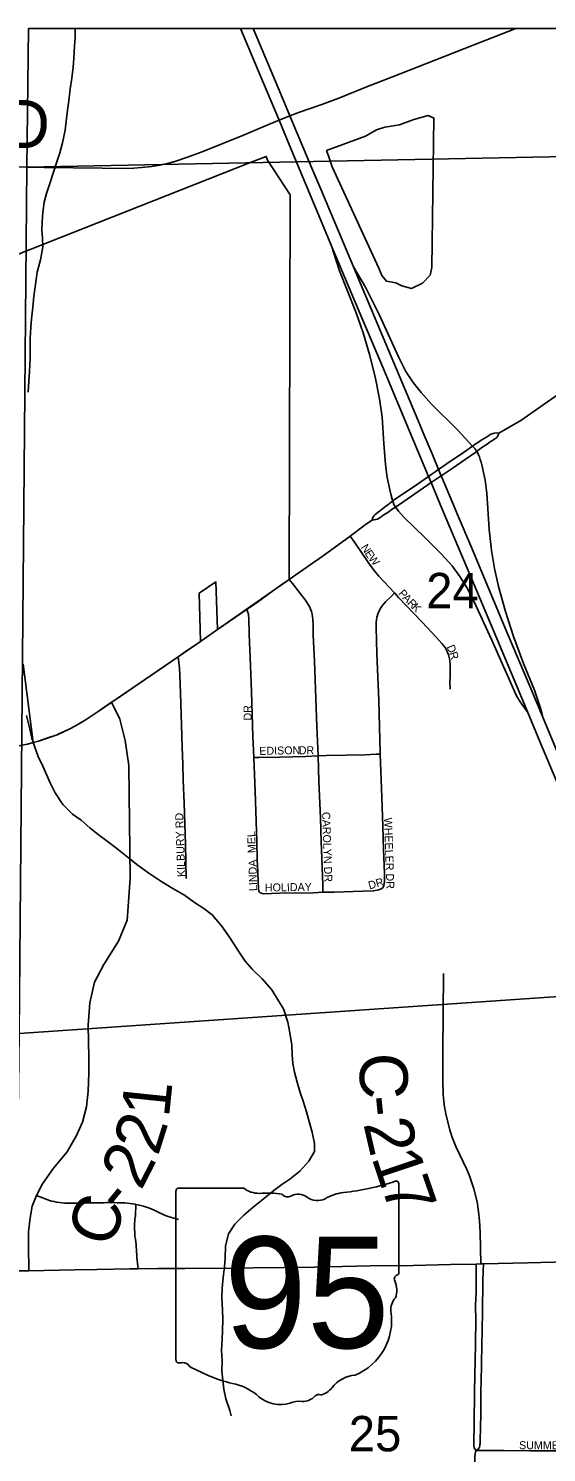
# Model space of a CAD drawing. Extents: x -9.1 to 34, y -3.1 to 22.
# Drawn here: x 7.252 to 7.865, y 19.215 to 20.9 of the extents above; entities that cross this region are included whole.
import ezdxf

# ---------------------------------------------------------------- set-up
doc = ezdxf.new("R2010")
doc.units = 0
for name, color, linetype in [('GM_X_Corporation', 7, 'Continuous'), ('GM_X_County_Road', 7, 'Continuous'), ('GM_X_County_Road_Text', 7, 'Continuous'), ('GM_X_Interchange_Ramps', 7, 'Continuous'), ('GM_X_Minor_Lake', 7, 'Continuous'), ('GM_X_Minor_River', 7, 'Continuous'), ('GM_X_Section', 7, 'Continuous'), ('GM_X_Section_Text', 7, 'Continuous'), ('GM_X_State_Location', 7, 'Continuous'), ('GM_X_State_Route', 7, 'Continuous'), ('GM_X_State_Shield', 7, 'Continuous'), ('GM_X_Township_Road', 7, 'Continuous'), ('GM_X_Township_Subdivision', 7, 'Continuous'), ('GM_X_Township_Subdivision_Text', 7, 'Continuous'), ('GM_X_US_Route', 7, 'Continuous')]:
    doc.layers.add(name, color=color, linetype=linetype)

msp = doc.modelspace()

# ---------------------------------------------------------------- linework, layer by layer
at = {"layer": 'GM_X_Corporation'}
msp.add_lwpolyline([(7.2455, 20.1477), (7.2573, 20.0548), (7.2636, 20.0565), (7.2747, 20.0604), (7.2857, 20.0642), (7.2875, 20.065), (7.2997, 20.0707), (7.308, 20.075), (7.3133, 20.0782), (7.3187, 20.0813), (7.3343, 20.0916), (7.4289, 20.1565), (7.4552, 20.1744), (7.4538, 20.2315), (7.4735, 20.2449), (7.4756, 20.1885), (7.5601, 20.2479), (7.5614, 20.7031), (7.5347, 20.7443), (7.5331, 20.7485), (7.5132, 20.7408), (6.9954, 20.5365)], dxfattribs=at)
at = {"layer": 'GM_X_County_Road'}
for points in [[(7.2303, 20.7363), (7.2707, 20.7355), (7.3391, 20.7345), (7.3639, 20.7343), (7.3763, 20.7346), (7.3856, 20.7353), (7.3979, 20.7368), (7.407, 20.7383), (7.4161, 20.7403), (7.425, 20.7427), (7.4398, 20.7475), (7.4572, 20.754), (7.5062, 20.7738), (7.5349, 20.7858), (7.5483, 20.7914), (7.555, 20.7942), (7.5612, 20.7966), (7.5725, 20.8008), (7.5989, 20.8099), (7.6192, 20.8177), (7.6509, 20.8305), (7.6828, 20.8428), (7.732, 20.8621), (7.7783, 20.8802), (7.8286, 20.9)], [(7.2612, 19.5187), (7.2682, 19.5324), (7.2812, 19.5513), (7.2973, 19.5705), (7.3086, 19.5898), (7.3156, 19.6057), (7.3203, 19.6237), (7.3225, 19.6423), (7.323, 19.6636), (7.3233, 19.6821), (7.3224, 19.7204), (7.3242, 19.7469), (7.3297, 19.7714), (7.3408, 19.7923), (7.3581, 19.8199), (7.3686, 19.8448), (7.3722, 19.894), (7.3705, 20.0279), (7.3661, 20.0572), (7.36, 20.0827), (7.3501, 20.1025)], [(7.7424, 19.6881), (7.743, 19.7814)], [(7.7873, 19.4379), (7.7864, 19.475), (7.7857, 19.4887), (7.7846, 19.4998), (7.7827, 19.5113), (7.7788, 19.5267), (7.7736, 19.5421), (7.7705, 19.5496), (7.7577, 19.5767), (7.753, 19.5885), (7.7504, 19.5967), (7.7462, 19.6134), (7.7439, 19.626), (7.7427, 19.6385), (7.7422, 19.6553), (7.7424, 19.6881)], [(7.2521, 19.4298), (7.2518, 19.4597), (7.2518, 19.4759), (7.2535, 19.4922), (7.2561, 19.5063), (7.2612, 19.5187)], [(7.2612, 19.5187), (7.2766, 19.5128), (7.279, 19.5122), (7.2821, 19.5115), (7.2849, 19.511), (7.2883, 19.5105), (7.2914, 19.5102), (7.2947, 19.5099), (7.2976, 19.5097), (7.3007, 19.5097), (7.3038, 19.5098), (7.3069, 19.5098), (7.31, 19.5098), (7.3131, 19.5099), (7.3162, 19.5099), (7.3193, 19.51), (7.3224, 19.51), (7.3256, 19.5101), (7.3287, 19.5101), (7.3318, 19.5101), (7.3349, 19.5102), (7.338, 19.5103), (7.3411, 19.5103), (7.3442, 19.5104), (7.3473, 19.5104), (7.3504, 19.5105), (7.3535, 19.5106), (7.3566, 19.5103), (7.3599, 19.5103), (7.3629, 19.5102), (7.3658, 19.51), (7.3688, 19.5098), (7.3718, 19.5095), (7.3747, 19.509), (7.3776, 19.5085), (7.3787, 19.5083)], [(7.3816, 19.432), (7.38, 19.4454), (7.3801, 19.449), (7.3795, 19.4519), (7.3795, 19.4549), (7.3793, 19.4578), (7.3791, 19.4607), (7.3788, 19.4636), (7.3784, 19.4671), (7.3777, 19.4701), (7.3777, 19.4732), (7.3774, 19.4759), (7.3772, 19.4786), (7.3771, 19.4828), (7.3772, 19.4856), (7.3774, 19.4884), (7.3776, 19.4912), (7.3784, 19.4949), (7.3787, 19.5083)]]:
    msp.add_lwpolyline(points, dxfattribs=at)
at = {"layer": 'GM_X_Interchange_Ramps'}
for points in [[(7.6109, 20.6417), (7.6158, 20.6252), (7.6198, 20.6133), (7.6397, 20.5634), (7.6479, 20.5399), (7.6559, 20.5131), (7.6625, 20.4859), (7.6673, 20.4615), (7.6702, 20.4399), (7.6724, 20.4089), (7.6743, 20.3841), (7.6764, 20.3687), (7.6803, 20.3505), (7.6807, 20.3489), (7.6821, 20.343), (7.6829, 20.3408), (7.6844, 20.3368)], [(7.7803, 20.4023), (7.7788, 20.404), (7.7772, 20.4057), (7.7595, 20.4248), (7.7289, 20.4553), (7.7165, 20.4691), (7.707, 20.4812), (7.6986, 20.4941), (7.69, 20.5105), (7.667, 20.5614), (7.6605, 20.5743), (7.6506, 20.5939), (7.6364, 20.6178)], [(7.8607, 20.0848), (7.8578, 20.0956), (7.8536, 20.1084), (7.8508, 20.1167), (7.8376, 20.1483), (7.8257, 20.1803), (7.8163, 20.2098), (7.808, 20.2397), (7.8034, 20.2608), (7.7999, 20.2823), (7.7971, 20.3069), (7.7945, 20.3502), (7.7924, 20.3655), (7.7884, 20.3837), (7.7875, 20.3868), (7.7866, 20.3898), (7.7855, 20.3929), (7.7846, 20.3953), (7.7836, 20.3975), (7.7823, 20.3995), (7.7814, 20.4008), (7.7803, 20.4023)], [(7.6844, 20.3368), (7.6859, 20.3341), (7.6862, 20.3336), (7.6881, 20.3309), (7.6899, 20.3286), (7.696, 20.3215), (7.7208, 20.2977), (7.7407, 20.2778), (7.7531, 20.2639), (7.7625, 20.2514), (7.7708, 20.2382), (7.7795, 20.2216), (7.8002, 20.1761), (7.8296, 20.1103), (7.8338, 20.1031), (7.8428, 20.0904)]]:
    msp.add_lwpolyline(points, dxfattribs=at)
at = {"layer": 'GM_X_Minor_Lake'}
for points in [[(7.6045, 20.7554), (7.6071, 20.7482), (7.6112, 20.7364), (7.6616, 20.6267), (7.6665, 20.6164), (7.6699, 20.6077), (7.6755, 20.6009), (7.6865, 20.5989), (7.6937, 20.5955), (7.7051, 20.5924), (7.7183, 20.5984), (7.7271, 20.6082), (7.729, 20.6173), (7.7316, 20.7939), (7.7248, 20.797), (7.7077, 20.7921), (7.691, 20.7861), (7.6736, 20.7832), (7.6637, 20.7802), (7.6508, 20.7726)], [(7.6508, 20.7726), (7.6045, 20.7554)]]:
    msp.add_lwpolyline(points, dxfattribs=at)
at = {"layer": 'GM_X_Minor_River'}
for points in [[(7.2658, 20.6263), (7.2686, 20.6415), (7.2682, 20.6517), (7.2675, 20.6612), (7.2679, 20.671), (7.2687, 20.6824), (7.2703, 20.6945), (7.273, 20.7047), (7.2779, 20.7187), (7.281, 20.7286), (7.2852, 20.7422), (7.2887, 20.7528), (7.2921, 20.7645), (7.2952, 20.7797), (7.2968, 20.7933), (7.298, 20.8032), (7.2995, 20.8145), (7.3011, 20.8286), (7.3031, 20.8411), (7.3046, 20.8543), (7.3054, 20.8646), (7.3062, 20.8793), (7.307, 20.8888), (7.3071, 20.9)], [(7.2512, 20.4695), (7.252, 20.4827), (7.2528, 20.4941), (7.2536, 20.51), (7.2537, 20.5335), (7.2545, 20.546), (7.2553, 20.5562), (7.2569, 20.5702), (7.2581, 20.5831), (7.26, 20.5971), (7.262, 20.6115), (7.2658, 20.6263)], [(7.4811, 19.4092), (7.4823, 19.4217), (7.4838, 19.4342), (7.4846, 19.4445), (7.4851, 19.4589), (7.4885, 19.4733), (7.4958, 19.485), (7.5068, 19.4955), (7.5178, 19.505), (7.5315, 19.5159), (7.5422, 19.5246), (7.5517, 19.5318), (7.5612, 19.5382), (7.573, 19.5476), (7.5836, 19.5593), (7.5901, 19.571), (7.5901, 19.5805), (7.5875, 19.5938), (7.5845, 19.6048), (7.5808, 19.6177), (7.5767, 19.6306), (7.5733, 19.6405), (7.5699, 19.653), (7.5666, 19.6647), (7.5647, 19.675), (7.564, 19.6852), (7.5633, 19.6966), (7.5611, 19.7114), (7.5588, 19.7239), (7.5536, 19.7398), (7.5476, 19.7493), (7.5397, 19.7623), (7.5283, 19.7752), (7.5166, 19.7866), (7.5083, 19.7961), (7.4996, 19.809), (7.4906, 19.8235), (7.48, 19.8379), (7.4691, 19.8508), (7.4593, 19.8584), (7.4483, 19.8657), (7.4362, 19.8741), (7.4226, 19.8821), (7.4094, 19.8901), (7.3942, 19.9004), (7.3814, 19.9095), (7.37, 19.9183), (7.3564, 19.9293), (7.3447, 19.9381), (7.3341, 19.9461), (7.3243, 19.9541), (7.3141, 19.9629), (7.3039, 19.9701), (7.2922, 19.9815), (7.2831, 19.9952), (7.2775, 20.0073), (7.2685, 20.0271), (7.2632, 20.0385), (7.2591, 20.0495), (7.2557, 20.0601), (7.2524, 20.0741), (7.2494, 20.087)], [(7.4918, 19.2581), (7.49, 19.2644), (7.4855, 19.2781), (7.4829, 19.2894), (7.4818, 19.3001), (7.4807, 19.3111), (7.4808, 19.3232), (7.48, 19.3357), (7.4808, 19.3482), (7.4813, 19.3588), (7.4817, 19.3725), (7.4814, 19.3831), (7.4807, 19.3979), (7.4811, 19.4092)]]:
    msp.add_lwpolyline(points, dxfattribs=at)
at = {"layer": 'GM_X_Section'}
msp.add_line((8.2709, 20.9), (7.2516, 20.9), dxfattribs=at)
msp.add_lwpolyline([(7.2516, 20.9), (7.2498, 20.7358), (8.2683, 20.7561), (8.2692, 20.7856), (8.2709, 20.9)], dxfattribs=at)
for points in [[(8.2683, 20.7561), (8.2596, 19.7802), (7.2408, 19.7107), (7.2498, 20.7358)], [(8.2596, 19.7802), (8.2596, 19.773), (8.2465, 18.7547), (7.2285, 18.7534), (7.2408, 19.7107)]]:
    msp.add_lwpolyline(points, close=True, dxfattribs=at)
at = {"layer": 'GM_X_State_Route'}
for points in [[(7.7994, 20.4114), (7.8009, 20.4123), (7.8039, 20.4142), (7.806, 20.4161), (7.8074, 20.4177), (7.8085, 20.4211), (7.8347, 20.436), (7.8702, 20.4608), (7.8818, 20.4692)], [(7.6585, 20.3181), (7.6591, 20.3201), (7.6599, 20.322), (7.6611, 20.3237), (7.6622, 20.3248), (7.6635, 20.326), (7.6655, 20.3274), (7.6687, 20.3299), (7.6732, 20.3333), (7.6771, 20.3363), (7.6829, 20.3408), (7.6851, 20.3424), (7.7081, 20.358), (7.7252, 20.3698), (7.7372, 20.3782), (7.7461, 20.3844), (7.7665, 20.3983), (7.7772, 20.4057), (7.7818, 20.4088), (7.7843, 20.4105), (7.7876, 20.4127), (7.7912, 20.4149), (7.7961, 20.418), (7.7983, 20.4193), (7.8005, 20.4202), (7.8029, 20.4209), (7.8054, 20.4213), (7.8085, 20.4211)], [(7.7243, 20.3597), (7.7278, 20.3622), (7.7283, 20.3625), (7.7404, 20.3707), (7.7533, 20.3794), (7.7686, 20.3898), (7.7823, 20.3995), (7.7838, 20.4005), (7.7897, 20.4047), (7.7947, 20.4082), (7.7981, 20.4106), (7.7994, 20.4114)], [(7.6862, 20.3336), (7.6866, 20.3338), (7.6897, 20.3358), (7.7243, 20.3597)], [(7.6712, 20.3235), (7.6724, 20.3243), (7.677, 20.3273), (7.6824, 20.331), (7.6862, 20.3336)], [(7.5601, 20.2479), (7.5892, 20.268), (7.5966, 20.273), (7.6023, 20.2769), (7.6094, 20.282), (7.6327, 20.2993), (7.652, 20.3136), (7.6585, 20.3181), (7.6606, 20.3184), (7.663, 20.3188), (7.6647, 20.3194), (7.6668, 20.3206), (7.6691, 20.322), (7.6712, 20.3235)], [(7.4756, 20.1885), (7.5105, 20.2126), (7.5212, 20.22), (7.5421, 20.2352), (7.5518, 20.242), (7.5601, 20.2479)], [(7.2573, 20.0548), (7.2636, 20.0565), (7.2857, 20.0642), (7.2997, 20.0707), (7.308, 20.075), (7.3187, 20.0813), (7.3343, 20.0916), (7.3501, 20.1025), (7.3528, 20.1043), (7.4289, 20.1565), (7.4371, 20.1622), (7.4552, 20.1744)], [(7.4552, 20.1744), (7.4756, 20.1885)], [(7.1198, 20.0443), (7.1539, 20.0455), (7.1741, 20.0463), (7.1787, 20.0465), (7.2189, 20.0481), (7.2232, 20.0484), (7.2265, 20.0487), (7.2279, 20.0489), (7.2326, 20.0495), (7.2373, 20.0503), (7.244, 20.0517), (7.2506, 20.0531), (7.2573, 20.0548)], [(7.2371, 19.4295), (7.2521, 19.4298), (7.3063, 19.4308), (7.3325, 19.4312), (7.3715, 19.4319), (7.3816, 19.432), (7.4047, 19.4322), (7.4367, 19.4325), (7.4945, 19.4328), (7.5181, 19.433), (7.5904, 19.4341), (7.6565, 19.4354), (7.7071, 19.436), (7.7511, 19.437), (7.7815, 19.4377), (7.7873, 19.4379)], [(7.7873, 19.4379), (7.7905, 19.438), (7.8426, 19.4392), (7.9538, 19.4418), (7.967, 19.4423), (7.9821, 19.4429), (8.0553, 19.4445)]]:
    msp.add_lwpolyline(points, dxfattribs=at)
at = {"layer": 'GM_X_State_Shield'}
for p, q in [((7.4263, 19.5242), (7.4263, 19.3241)), ((7.5061, 19.5276), (7.4289, 19.5276)), ((7.69, 19.4279), (7.69, 19.5326)), ((7.69, 19.4279), (7.69, 19.4279))]:
    msp.add_line(p, q, dxfattribs=at)
for centre, radius, start, end in [((7.5961, 19.8005), 0.2796, 275.8445, 288.9065), ((7.6871, 19.533), 0.00294, 351.8621, 97.738), ((7.4294, 19.5246), 0.00305, 98.1301, 188.1301), ((7.5245, 19.5509), 0.0296, 231.6195, 271.1119), ((7.5344, 19.4153), 0.1064, 80.4867, 94.9883), ((7.5585, 19.5256), 0.00855, 219.7921, 297.1024), ((7.5711, 19.5025), 0.0178, 54.4667, 119.1411), ((7.594, 19.5342), 0.0214, 233.8562, 294.8282), ((7.6317, 19.4665), 0.0563, 97.3462, 120.7689), ((7.6893, 19.4202), 0.00454, 107.944, 210.337), ((7.6604, 19.407), 0.0273, 340.033, 23.6496), ((7.6869, 19.4275), 0.00314, 289.6038, 7.7341), ((7.7005, 19.3841), 0.0198, 136.8065, 186.9296), ((7.6117, 19.3708), 0.0699, 292.3089, 8.9858), ((7.4294, 19.3236), 0.00308, 171.9584, 258.3066), ((7.4299, 19.3441), 0.0235, 267.339, 280.6039), ((7.4347, 19.3125), 0.00848, 29.7484, 93.2717), ((7.5417, 19.4923), 0.2019, 240.4129, 257.1985), ((7.6412, 19.2679), 0.0383, 94.4031, 142.5768), ((7.4815, 19.2342), 0.0632, 47.1842, 75.836), ((7.5759, 19.2965), 0.0214, 268.777, 315.5493), ((7.5953, 19.2772), 0.00601, 65.7517, 132.6484), ((7.5927, 19.3047), 0.0226, 282.8732, 323.2771), ((7.5499, 19.3115), 0.0401, 230.7004, 286.2918), ((7.573, 19.2423), 0.0329, 85.6951, 111.2099)]:
    msp.add_arc(centre, radius, start, end, dxfattribs=at)
at = {"layer": 'GM_X_Township_Road'}
for points in [[(7.3787, 19.5083), (7.3812, 19.5078), (7.3843, 19.507), (7.3877, 19.5061), (7.3913, 19.5049), (7.3948, 19.5037), (7.3976, 19.5026), (7.4003, 19.5014), (7.4022, 19.5005), (7.4043, 19.4995), (7.4069, 19.4982), (7.4094, 19.4969), (7.412, 19.4958), (7.4146, 19.4948), (7.4172, 19.4938), (7.4291, 19.4905)], [(7.78, 19.2965), (7.7801, 19.3087), (7.7803, 19.3209), (7.7811, 19.3704), (7.781, 19.389), (7.7816, 19.4044), (7.7815, 19.4294), (7.7815, 19.4377)], [(7.7875, 19.2964), (7.788, 19.3211), (7.7892, 19.3804), (7.7895, 19.4178), (7.7901, 19.4293), (7.7905, 19.438)], [(7.7817, 19.217), (7.7798, 19.2192), (7.7793, 19.2207), (7.7791, 19.2225), (7.779, 19.2238), (7.7794, 19.2509), (7.7798, 19.2849), (7.7799, 19.296), (7.78, 19.2965)], [(7.7817, 19.217), (7.7834, 19.2181), (7.7847, 19.2195), (7.7857, 19.221), (7.786, 19.2227), (7.7862, 19.224), (7.7864, 19.2254), (7.7865, 19.2306), (7.7868, 19.2427), (7.7874, 19.2618), (7.7873, 19.2899), (7.7875, 19.2964)]]:
    msp.add_lwpolyline(points, dxfattribs=at)
at = {"layer": 'GM_X_Township_Subdivision'}
for points in [[(7.6849, 20.2319), (7.6665, 20.2518), (7.6606, 20.259), (7.6533, 20.2689), (7.6376, 20.2921), (7.6327, 20.2993)], [(7.5945, 20.0391), (7.5932, 20.0738), (7.5903, 20.151), (7.5889, 20.1818), (7.5888, 20.1942), (7.5884, 20.2005), (7.5876, 20.2068), (7.5868, 20.2099), (7.5856, 20.2129), (7.5842, 20.2157), (7.5792, 20.2237), (7.5642, 20.2433), (7.5601, 20.2479)], [(7.6647, 20.2051), (7.665, 20.206), (7.6674, 20.2116), (7.6689, 20.2142), (7.6705, 20.2168), (7.6723, 20.2192), (7.6743, 20.2214), (7.6809, 20.2279), (7.6849, 20.2319)], [(7.7508, 20.1317), (7.7509, 20.1461), (7.7505, 20.1524), (7.7499, 20.1556), (7.7491, 20.1587), (7.7479, 20.1616), (7.7464, 20.1645), (7.7448, 20.1672), (7.741, 20.1722), (7.7347, 20.1792), (7.7177, 20.1974), (7.6899, 20.2267), (7.6849, 20.2319)], [(7.5184, 20.0371), (7.5173, 20.0622), (7.5156, 20.1149), (7.5146, 20.1459), (7.5131, 20.1831), (7.5125, 20.2025), (7.5123, 20.2048), (7.512, 20.2068), (7.5111, 20.21), (7.5105, 20.2126)], [(7.668, 20.0412), (7.668, 20.0426), (7.6673, 20.0736), (7.6663, 20.1045), (7.664, 20.1601), (7.6638, 20.1756), (7.6632, 20.1911), (7.6632, 20.1972), (7.6635, 20.2002), (7.6641, 20.2031), (7.6647, 20.2051)], [(7.4384, 19.8939), (7.4376, 19.9341), (7.4358, 19.9831), (7.4348, 20.0107), (7.4344, 20.0292), (7.4338, 20.0496), (7.4325, 20.0885), (7.4315, 20.1134), (7.431, 20.1351), (7.4305, 20.1429), (7.4297, 20.1496), (7.4289, 20.1565)], [(7.751, 20.1182), (7.7507, 20.1275), (7.7508, 20.1317)], [(7.5945, 20.0391), (7.6045, 20.0396), (7.6508, 20.0405), (7.6631, 20.041), (7.668, 20.0412)], [(7.6711, 19.8831), (7.6725, 19.8853), (7.6729, 19.8878), (7.6732, 19.8911), (7.673, 19.9004), (7.672, 19.9282), (7.6712, 19.9561), (7.6699, 19.9901), (7.6688, 20.021), (7.668, 20.0412)], [(7.5184, 20.0371), (7.5244, 20.0372), (7.5491, 20.0376), (7.5799, 20.0384), (7.5945, 20.0391)], [(7.5258, 19.8772), (7.5247, 19.8782), (7.5242, 19.8795), (7.524, 19.8808), (7.5232, 19.901), (7.5226, 19.9165), (7.5222, 19.9382), (7.52, 19.9971), (7.5184, 20.0371)], [(7.6003, 19.8776), (7.6, 19.8867), (7.5982, 19.9376), (7.5973, 19.9656), (7.5954, 20.0088), (7.5945, 20.0391)], [(7.5258, 19.8772), (7.527, 19.8766), (7.5284, 19.8762), (7.53, 19.876), (7.5487, 19.8765), (7.589, 19.8772), (7.6003, 19.8776)], [(7.6003, 19.8776), (7.6137, 19.8779), (7.6477, 19.8789), (7.6601, 19.8795), (7.6663, 19.8804), (7.6691, 19.8816), (7.6711, 19.8831)], [(7.7817, 19.217), (7.7809, 19.2151), (7.7806, 19.2133), (7.7802, 19.2092), (7.7801, 19.2065), (7.7794, 19.1848), (7.7796, 19.1786), (7.7798, 19.1713), (7.7801, 19.1694), (7.7806, 19.1663), (7.7825, 19.1604), (7.7829, 19.1581)], [(7.7817, 19.217), (7.7961, 19.217), (7.8045, 19.2171), (7.8148, 19.217), (7.8458, 19.2167), (7.8769, 19.2165), (7.9079, 19.2162), (7.9092, 19.2162)]]:
    msp.add_lwpolyline(points, dxfattribs=at)
at = {"layer": 'GM_X_US_Route'}
for points in [[(7.9874, 19.7467), (7.8572, 20.0561), (7.8428, 20.0904), (7.8092, 20.1707), (7.7754, 20.2509), (7.7415, 20.331), (7.7283, 20.3625), (7.7252, 20.3698), (7.7078, 20.4112), (7.6718, 20.4972), (7.6465, 20.5574), (7.6109, 20.6417), (7.5995, 20.6691), (7.5611, 20.7608), (7.5483, 20.7914), (7.5299, 20.8353), (7.5027, 20.9)], [(7.5391, 20.8493), (7.5177, 20.9)], [(7.5584, 20.8032), (7.5524, 20.8177), (7.5391, 20.8493)], [(7.5778, 20.7571), (7.5612, 20.7966), (7.5584, 20.8032)], [(7.5976, 20.71), (7.5873, 20.7346), (7.5778, 20.7571)], [(7.7191, 20.4214), (7.7126, 20.4368), (7.6716, 20.5341), (7.6475, 20.5914), (7.6364, 20.6178), (7.5976, 20.71)], [(7.7295, 20.3965), (7.7191, 20.4214)], [(7.7462, 20.3569), (7.7451, 20.3594), (7.7404, 20.3707), (7.7372, 20.3782), (7.7295, 20.3965)], [(7.7605, 20.3227), (7.7462, 20.3569)], [(7.9207, 19.9418), (7.8955, 20.0014), (7.8607, 20.0848), (7.8464, 20.1189), (7.8172, 20.1875), (7.7752, 20.2878), (7.7605, 20.3227)]]:
    msp.add_lwpolyline(points, dxfattribs=at)

# ---------------------------------------------------------------- texts
at = {"layer": 'GM_X_County_Road_Text'}
for s, height, rotation, p in [('FAIRGROUND', 0.05682, 358.5316, (6.7657, 20.7708)), ('C', 0.0568, 270.2693, (7.6438, 19.6875)), ('1', 0.0568, 84.05, (7.4179, 19.6101)), ('-', 0.0568, 275.6331, (7.6443, 19.6351)), ('2', 0.0568, 72.5665, (7.4049, 19.5646)), ('2', 0.0568, 283.015, (7.6479, 19.6039)), ('2', 0.0568, 62.8504, (7.3849, 19.5237)), ('1', 0.0568, 288.5937, (7.6574, 19.564)), ('7', 0.0568, 289.1167, (7.6688, 19.5303)), ('C', 0.0568, 70.3937, (7.3495, 19.455)), ('-', 0.0568, 50.3843, (7.3626, 19.4945))]:
    msp.add_text(s, height=height, rotation=rotation, dxfattribs=at).set_placement(p)
at = {"layer": 'GM_X_Section_Text'}
for s, p in [('24', (7.7225, 20.2138)), ('25', (7.6308, 19.216))]:
    msp.add_text(s, height=0.04186, rotation=0, dxfattribs=at).set_placement(p)
at = {"layer": 'GM_X_State_Location'}
for s in ['s', 'r']:
    msp.add_text(s, height=0.000189, dxfattribs=at).set_placement((7.5552, 19.4108))
msp.add_text('95', height=0.000189, rotation=0, dxfattribs=at).set_placement((7.5075, 19.397))
at = {"layer": 'GM_X_State_Shield'}
msp.add_text('95', height=0.13184, dxfattribs=at).set_placement((7.4832, 19.3382))
at = {"layer": 'GM_X_Township_Subdivision_Text'}
for s, rotation, p in [('N', 302.4108, (7.6448, 20.286)), ('E', 302.379, (7.6493, 20.279)), ('W', 308.6948, (7.6535, 20.2725)), ('P', 310.3968, (7.689, 20.231)), ('A', 313.757, (7.6938, 20.2255)), ('R', 314.0644, (7.6996, 20.2194)), ('K', 314.0573, (7.7048, 20.2141)), ('D', 292.2316, (7.7466, 20.1683)), ('R', 286.9063, (7.7497, 20.1608)), ('DR', 90, (7.5158, 20.0809)), ('EDISON', 1.1227, (7.525, 20.0402)), ('DR', 0, (7.5717, 20.041)), ('CAROLYN DR', 271.91, (7.5993, 19.9726)), ('KILBURY RD', 92.0442, (7.4374, 19.8959)), ('WHEELER DR', 271.9296, (7.6726, 19.9659)), ('MEL', 91.9736, (7.5208, 19.9242)), ('LINDA', 91.3013, (7.5224, 19.8792)), ('HOLIDAY', 0.9089, (7.5316, 19.8785)), ('DR', 15.5147, (7.6554, 19.881)), ('SUMMERSET', 0, (7.8325, 19.2185))]:
    msp.add_text(s, height=0.00947, rotation=rotation, dxfattribs=at).set_placement(p)

doc.saveas('drawing.dxf')
